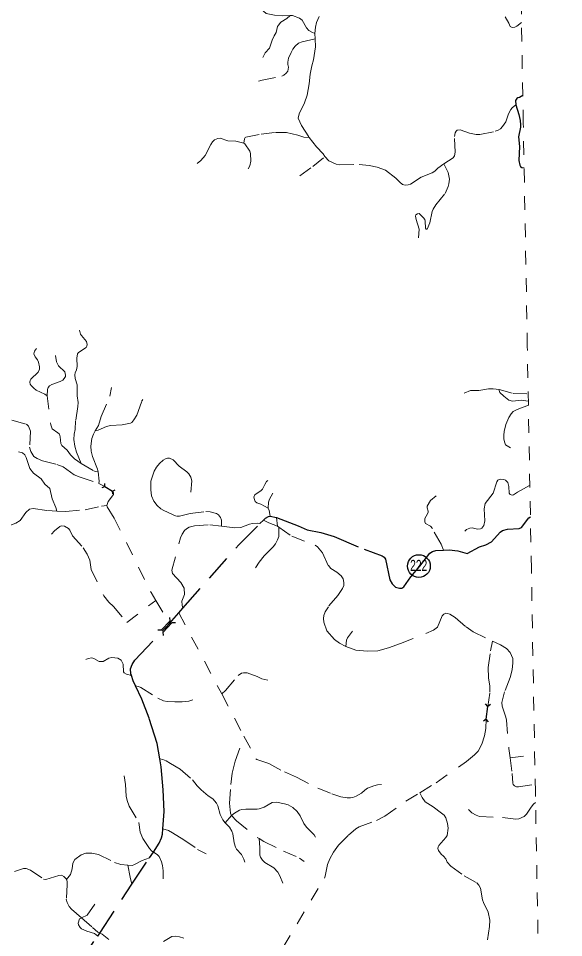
# Model space of a CAD drawing. Extents: x 220.8 to 246.7, y 7287.6 to 7315.8.
# Drawn here: x 242.67 to 246.65, y 7298.43 to 7305.15 of the extents above; entities that cross this region are included whole.
import ezdxf
from ezdxf.enums import TextEntityAlignment as Align

# ---------------------------------------------------------------- set-up
doc = ezdxf.new("R2010")
doc.units = 0
doc.header["$LTSCALE"] = 0.032
for name, pattern in [('DOTTED', [1.5, 0.3, -1.2]), ('LONG_DASHED', [7.5, 6, -1.5]), ('MEDIUM_DASHED', [4.5, 3, -1.5]), ('SHORT_DASHED', [2.7, 1.5, -1.2])]:
    doc.linetypes.add(name, pattern=pattern)
for name, color, linetype, lineweight in [('10', 7, 'Continuous', 25), ('13', 7, 'Continuous', 25), ('31', 7, 'Continuous', 25), ('35', 7, 'SHORT_DASHED', 13), ('4', 7, 'LONG_DASHED', 25), ('6', 7, 'MEDIUM_DASHED', 13), ('7', 7, 'DOTTED', 13)]:
    doc.layers.add(name, color=color, linetype=linetype, lineweight=lineweight)
doc.layers.add('61', color=7, linetype='Continuous')

msp = doc.modelspace()

# ---------------------------------------------------------------- linework, layer by layer
at = {"layer": '10'}
for p, q in [((243.7275, 7300.6631), (243.7911, 7300.7302)), ((243.8161, 7300.7308), (243.7911, 7300.7302)), ((243.7129, 7300.6769), (243.6881, 7300.6764)), ((243.7281, 7300.6383), (243.7275, 7300.6631))]:
    msp.add_line(p, q, dxfattribs=at)
msp.add_lwpolyline([(243.7129, 7300.6769), (243.7766, 7300.7439), (243.776, 7300.769)], dxfattribs=at)
at = {"layer": '13'}
msp.add_circle((245.5943, 7301.145), 0.083, dxfattribs=at)
at = {"layer": '31'}
for p, q in [((243.282, 7301.7179), (243.3016, 7301.7267)), ((243.3016, 7301.7267), (243.3001, 7301.7482)), ((243.3016, 7301.7267), (243.3571, 7301.6934)), ((243.3571, 7301.6934), (243.3768, 7301.7021)), ((243.3586, 7301.6719), (243.3571, 7301.6934)), ((246.0963, 7300.118), (246.0807, 7300.1376)), ((246.0861, 7300.0261), (246.0963, 7300.118)), ((246.1158, 7300.1337), (246.0963, 7300.118)), ((246.0861, 7300.0261), (246.0665, 7300.0107)), ((246.1016, 7300.0067), (246.0861, 7300.0261))]:
    msp.add_line(p, q, dxfattribs=at)
at = {"layer": '35'}
msp.add_lwpolyline([(246.6507, 7288.0853), (246.6212, 7289.7146), (246.5917, 7291.3439), (246.5622, 7292.9732), (246.5328, 7294.6024), (246.5034, 7296.2317), (246.4739, 7297.861), (246.4446, 7299.4903), (246.4152, 7301.1196), (246.3858, 7302.7489), (246.3565, 7304.3782), (246.3272, 7306.0075), (246.2979, 7307.6367), (246.2685, 7309.266), (246.2393, 7310.8953), (246.21, 7312.5246), (246.1808, 7314.1539), (246.1516, 7315.7832)], dxfattribs=at)
at = {"layer": '4'}
for points in [[(246.3528, 7304.5841), (246.3283, 7304.5682), (246.3174, 7304.5671), (246.3098, 7304.5606), (246.3, 7304.5464), (246.3013, 7304.5153), (246.3235, 7304.4455), (246.3337, 7304.4017), (246.3357, 7304.369), (246.3357, 7304.3517), (246.3215, 7304.2814), (246.3276, 7304.2101), (246.3245, 7304.1081), (246.3317, 7304.0745), (246.3368, 7304.0653), (246.3449, 7304.0572), (246.3623, 7304.0553)], [(243.1124, 7298.2445), (243.2485, 7298.4414), (243.2641, 7298.4635), (243.4987, 7298.8213), (243.6276, 7299.0132), (243.6564, 7299.0554), (243.6974, 7299.1205), (243.7149, 7299.1594), (243.7212, 7299.187), (243.7243, 7299.2244), (243.735, 7299.3527), (243.7275, 7299.5096), (243.7124, 7299.679), (243.7024, 7299.7355), (243.6823, 7299.8485), (243.6233, 7300.033), (243.5719, 7300.1723), (243.5239, 7300.2701), (243.5066, 7300.3053), (243.4945, 7300.3445), (243.4903, 7300.358), (243.489, 7300.3932), (243.5003, 7300.4258), (243.5191, 7300.4572), (243.7477, 7300.6989), (243.7734, 7300.7262), (243.8408, 7300.8029), (243.8708, 7300.8371), (244.2797, 7301.3006), (244.4315, 7301.4549), (244.4589, 7301.4807), (244.4743, 7301.4951), (244.4956, 7301.5077), (244.5068, 7301.5085), (244.5538, 7301.4998), (244.7127, 7301.4399), (244.7793, 7301.4098), (244.8772, 7301.391), (244.9751, 7301.3621), (245.1934, 7301.268)], [(245.1934, 7301.268), (245.3265, 7301.219), (245.3415, 7301.209), (245.3491, 7301.1964), (245.3817, 7301.0433), (245.398, 7301.0157), (245.4244, 7300.9918), (245.452, 7300.9843), (245.4696, 7300.9843), (245.4834, 7300.9931), (245.5361, 7301.0671), (245.6013, 7301.145), (245.6741, 7301.2391), (245.693, 7301.2504), (245.7168, 7301.2592), (245.7727, 7301.262), (245.816, 7301.2642), (245.8775, 7301.2554), (245.9477, 7301.2366), (246.0369, 7301.2855), (246.0833, 7301.3006), (246.1235, 7301.3232), (246.1875, 7301.3922), (246.2033, 7301.4049), (246.2402, 7301.4135), (246.3268, 7301.4186), (246.3431, 7301.4274), (246.3958, 7301.4964), (246.4083, 7301.504)]]:
    msp.add_lwpolyline(points, dxfattribs=at)
at = {"layer": '6'}
msp.add_line((244.5625, 7301.4357), (244.5538, 7301.4998), dxfattribs=at)
for points in [[(244.0945, 7305.3468), (244.1381, 7305.3498), (244.2085, 7305.3353), (244.2743, 7305.3292), (244.2873, 7305.3269), (244.3316, 7305.2994), (244.3875, 7305.2887), (244.4051, 7305.2802), (244.415, 7305.2695), (244.4433, 7305.2198), (244.4594, 7305.1999), (244.48, 7305.1831), (244.5404, 7305.1693), (244.5948, 7305.1655), (244.653, 7305.1673), (244.6712, 7305.1678), (244.7217, 7305.1487), (244.7416, 7305.1326), (244.7722, 7305.0776), (244.7913, 7305.0592), (244.8112, 7305.0462), (244.8349, 7305.0363)], [(244.8349, 7305.0363), (244.838, 7305.0814), (244.8472, 7305.1158), (244.867, 7305.1617)], [(246.2246, 7305.1571), (246.2514, 7305.112), (246.2606, 7305.0883), (246.2759, 7305.0806), (246.295, 7305.0821), (246.3088, 7305.089), (246.3432, 7305.1158)], [(244.8349, 7305.0363), (244.8372, 7304.9963), (244.8382, 7304.9397), (244.8235, 7304.8451), (244.8114, 7304.8003), (244.8005, 7304.7396), (244.7929, 7304.6674), (244.7788, 7304.5862), (244.7584, 7304.53), (244.7187, 7304.4482), (244.7129, 7304.4173), (244.736, 7304.3651), (244.7929, 7304.277), (244.8459, 7304.2078), (244.8945, 7304.158), (244.9074, 7304.1384), (244.9367, 7304.1062), (244.9891, 7304.0819), (245.0179, 7304.0768), (245.1591, 7304.0787), (245.232, 7304.0723), (245.2882, 7304.0608), (245.3496, 7304.0385), (245.4263, 7303.979), (245.455, 7303.9496), (245.4755, 7303.9336), (245.4934, 7303.9292), (245.5151, 7303.9298), (245.5333, 7303.9349), (245.6094, 7303.9864), (245.6903, 7304.0186), (245.7101, 7304.0314), (245.7324, 7304.0532), (245.7751, 7304.085), (245.8449, 7304.1273), (245.8545, 7304.1433), (245.8584, 7304.1682), (245.8545, 7304.2833), (245.8584, 7304.3095), (245.8654, 7304.3229), (245.8731, 7304.3293), (245.8948, 7304.3325), (245.9632, 7304.3082), (246.0111, 7304.2992), (246.0399, 7304.2986), (246.1511, 7304.3216), (246.1728, 7304.3299), (246.1888, 7304.3401), (246.2054, 7304.3568), (246.2284, 7304.3913), (246.2495, 7304.4501), (246.2655, 7304.4808), (246.2751, 7304.4929), (246.3013, 7304.5153)], [(242.6205, 7302.2105), (242.7206, 7302.1845), (242.7317, 7302.1799), (242.7437, 7302.1679), (242.7585, 7302.13), (242.7511, 7302.0136), (242.7594, 7301.9812), (242.7825, 7301.9461), (242.8056, 7301.9304), (242.8454, 7301.9128), (242.9507, 7301.887), (242.996, 7301.8694), (243.0764, 7301.8112), (243.1198, 7301.7937), (243.258, 7301.7486), (243.3016, 7301.7267), (243.3571, 7301.6934), (243.3637, 7301.6791), (243.3629, 7301.6679), (243.3241, 7301.618), (243.3143, 7301.5888)], [(242.2041, 7301.3647), (242.2654, 7301.3816), (242.3503, 7301.4274), (242.373, 7301.4322), (242.42, 7301.4378), (242.5319, 7301.4283), (242.5809, 7301.4322), (242.6498, 7301.4593), (242.6833, 7301.4792), (242.7239, 7301.5366), (242.751, 7301.5613), (242.7773, 7301.5668), (242.8816, 7301.5501), (242.9508, 7301.5468), (243.0162, 7301.5437), (243.1572, 7301.5565), (243.2767, 7301.5836), (243.3143, 7301.5888)], [(243.3143, 7301.5888), (243.3182, 7301.5771), (243.3692, 7301.4961), (243.639, 7300.951), (243.6731, 7300.894), (243.7734, 7300.7262)], [(244.4589, 7301.4807), (244.4986, 7301.4609), (244.5625, 7301.4357)], [(244.5625, 7301.4357), (244.5718, 7301.4287), (244.6663, 7301.3637), (244.8356, 7301.2989), (244.8527, 7301.2858), (244.8902, 7301.241), (244.9328, 7301.1489), (244.9498, 7301.1273), (244.9947, 7301.1011), (245.026, 7301.0727), (245.0413, 7301.0506), (245.047, 7301.025), (245.0453, 7301.0028), (245.0368, 7300.9801), (245.0027, 7300.9289), (244.9328, 7300.8482), (244.9084, 7300.8102), (244.8998, 7300.7835), (244.8981, 7300.7619), (244.901, 7300.7363), (244.9214, 7300.6726), (244.9783, 7300.6079), (245.0135, 7300.5817), (245.0617, 7300.5564), (245.1328, 7300.5306), (245.2192, 7300.5226), (245.2931, 7300.5254), (245.3715, 7300.5476), (245.4585, 7300.5783), (245.7017, 7300.6766), (245.7307, 7300.6976), (245.7648, 7300.7823), (245.7756, 7300.7943), (245.7904, 7300.7999), (245.8034, 7300.7988), (245.8199, 7300.7926), (245.8591, 7300.7681), (245.9387, 7300.7005), (245.9904, 7300.6653), (246.1319, 7300.5962)], [(243.8408, 7300.8029), (244.1549, 7300.2103), (244.3169, 7299.902), (244.4038, 7299.7367), (244.4102, 7299.7313), (244.4976, 7299.7015), (244.6127, 7299.6407), (244.7002, 7299.6023), (244.8558, 7299.5213), (244.9582, 7299.4808), (245.0232, 7299.4595), (245.0701, 7299.452), (245.0936, 7299.4509), (245.1106, 7299.4541), (245.1362, 7299.4627), (245.1757, 7299.4861), (245.2002, 7299.5085), (245.2194, 7299.5213), (245.2641, 7299.5394), (245.2908, 7299.5469), (245.3207, 7299.5501)], [(245.6, 7299.4887), (245.7198, 7299.5615), (245.941, 7299.7171), (246.0008, 7299.7655), (246.0262, 7299.7925), (246.0541, 7299.8433), (246.0721, 7299.9056), (246.0828, 7299.9588), (246.0861, 7300.0261), (246.0963, 7300.118), (246.1123, 7300.2226), (246.1114, 7300.2685), (246.1016, 7300.3291), (246.1, 7300.4037), (246.1164, 7300.5249), (246.1319, 7300.5962)], [(246.1319, 7300.5962), (246.1893, 7300.57), (246.2343, 7300.543), (246.2606, 7300.5135), (246.281, 7300.4692), (246.281, 7300.4389), (246.2753, 7300.3873), (246.2597, 7300.3299), (246.2188, 7300.2267), (246.1999, 7300.1489), (246.2016, 7300.1202), (246.2294, 7300.0399), (246.2327, 7300.0203), (246.2507, 7299.813), (246.2596, 7299.7445), (246.2745, 7299.6303), (246.2794, 7299.5598), (246.2827, 7299.5484), (246.2917, 7299.5385), (246.3056, 7299.5328), (246.3204, 7299.5312), (246.4435, 7299.55)], [(244.6024, 7298.3604), (244.9039, 7298.8635), (244.9096, 7298.8798), (244.926, 7298.9634), (244.9432, 7299.006), (244.9694, 7299.0544), (245.0063, 7299.1068), (245.0792, 7299.1781), (245.1332, 7299.2248), (245.157, 7299.2403), (245.2848, 7299.287), (245.3463, 7299.3165), (245.4986, 7299.4271), (245.6, 7299.4887)], [(245.6, 7299.4887), (245.6177, 7299.4549), (245.6409, 7299.4229), (245.6991, 7299.3866), (245.7587, 7299.3401), (245.7783, 7299.3241), (245.7899, 7299.3059), (245.8023, 7299.263), (245.8074, 7299.231), (245.7994, 7299.1765), (245.7907, 7299.162), (245.7391, 7299.1039), (245.734, 7299.0937), (245.7332, 7299.0813), (245.7369, 7299.0661), (245.7558, 7299.0406), (245.7739, 7299.0261), (245.7907, 7299.005), (245.7994, 7298.9818), (245.827, 7298.9512), (245.9251, 7298.8808), (246.0181, 7298.8299), (246.0327, 7298.8139), (246.0436, 7298.7914), (246.0581, 7298.7071), (246.0646, 7298.686), (246.0995, 7298.6169), (246.1112, 7298.5566), (246.1104, 7298.5108), (246.0952, 7298.4142)], [(242.64, 7298.9125), (242.7058, 7298.9347), (242.7254, 7298.9356), (242.7582, 7298.9233), (242.854, 7298.8585), (242.8688, 7298.8561), (242.9655, 7298.8839), (242.9843, 7298.8856), (243.0015, 7298.8774), (243.0179, 7298.861), (243.0199, 7298.8552), (243.0253, 7298.8397), (243.0261, 7298.8176), (243.0195, 7298.7103), (243.0253, 7298.6873), (243.0408, 7298.6578), (243.0564, 7298.6382), (243.1292, 7298.574), (243.2112, 7298.503), (243.2506, 7298.471), (243.2641, 7298.4635), (243.2801, 7298.4546), (243.3292, 7298.417)], [(243.7282, 7298.4014), (243.7905, 7298.4383), (243.815, 7298.4407), (243.8462, 7298.4366), (243.8781, 7298.4252)]]:
    msp.add_lwpolyline(points, dxfattribs=at)
at = {"layer": '7'}
for p, q in [((246.2596, 7299.7445), (246.4396, 7299.767)), ((244.1789, 7299.2698), (244.2265, 7299.323))]:
    msp.add_line(p, q, dxfattribs=at)
for points in [[(244.4549, 7304.8601), (244.4708, 7304.8956), (244.5039, 7304.9301), (244.523, 7304.9879), (244.5365, 7305.02), (244.5514, 7305.0443), (244.5622, 7305.0872), (244.5678, 7305.0974), (244.5859, 7305.1184), (244.6298, 7305.145), (244.653, 7305.1673)], [(244.4237, 7304.6876), (244.4484, 7304.696), (244.592, 7304.7249), (244.6069, 7304.731), (244.6256, 7304.7459), (244.6358, 7304.7613), (244.6419, 7304.7897), (244.6363, 7304.8107), (244.6358, 7304.827), (244.6424, 7304.8569), (244.6605, 7304.8979), (244.6741, 7304.9221), (244.6908, 7304.9431), (244.716, 7304.965), (244.7417, 7304.9757), (244.8372, 7304.9963)], [(244.3146, 7304.2359), (244.3212, 7304.2673), (244.3248, 7304.2755), (244.33, 7304.2786), (244.4415, 7304.3002), (244.5479, 7304.313), (244.627, 7304.314), (244.7108, 7304.294), (244.7535, 7304.2781), (244.7929, 7304.277)], [(243.9748, 7304.0869), (244.0026, 7304.109), (244.0324, 7304.145), (244.074, 7304.2262), (244.0864, 7304.2447), (244.1023, 7304.2585), (244.1254, 7304.2688), (244.1424, 7304.2704), (244.1999, 7304.2524), (244.2585, 7304.2508), (244.3146, 7304.2359)], [(244.3146, 7304.2359), (244.3223, 7304.2298), (244.3593, 7304.1773), (244.3644, 7304.1588), (244.366, 7304.1023), (244.3593, 7304.0684), (244.348, 7304.0468)], [(244.7239, 7303.9973), (244.8203, 7304.0641), (244.9074, 7304.1384)], [(245.5902, 7303.5441), (245.5971, 7303.6069), (245.5735, 7303.6771), (245.5703, 7303.7007), (245.5725, 7303.7109), (245.5843, 7303.7194), (245.5971, 7303.72), (245.6271, 7303.6899), (245.6368, 7303.6771), (245.6405, 7303.6653), (245.6416, 7303.6133), (245.647, 7303.6063), (245.6545, 7303.6058), (245.6743, 7303.6535), (245.692, 7303.7355), (245.699, 7303.7532), (245.7177, 7303.7843), (245.7847, 7303.8679), (245.8083, 7303.9183), (245.8137, 7303.9371), (245.8164, 7303.9714), (245.8132, 7303.9971), (245.8078, 7304.0202), (245.7751, 7304.085)], [(243.1165, 7302.8675), (243.1233, 7302.84), (243.1296, 7302.8286), (243.1663, 7302.7866), (243.1719, 7302.7643), (243.1699, 7302.7508), (243.1649, 7302.7421), (243.1083, 7302.7049), (243.1018, 7302.6969), (243.0957, 7302.6629), (243.0979, 7302.6032), (243.0941, 7302.5797), (243.0846, 7302.5561), (243.0825, 7302.5425), (243.0834, 7302.5164), (243.0989, 7302.4683), (243.0979, 7302.3884), (243.1054, 7302.341), (243.1047, 7302.3103), (243.0875, 7302.2057), (243.0846, 7302.1421), (243.0769, 7302.1078), (243.075, 7302.0696), (243.0825, 7302.0218), (243.095, 7301.9768), (243.129, 7301.8941)], [(242.8011, 7302.7352), (242.7882, 7302.7146), (242.7831, 7302.6954), (242.7925, 7302.6736), (242.8096, 7302.6514), (242.8173, 7302.6352), (242.8241, 7302.6014), (242.8241, 7302.5843), (242.8135, 7302.5617), (242.76, 7302.5108), (242.7545, 7302.5005), (242.7528, 7302.4877), (242.7558, 7302.4745), (242.7622, 7302.4638), (242.7818, 7302.4437), (242.8002, 7302.4313), (242.8626, 7302.4014), (242.8797, 7302.3899)], [(242.8797, 7302.3899), (242.8816, 7302.4354), (242.8869, 7302.4491), (242.8971, 7302.4617), (242.9129, 7302.4715), (242.9743, 7302.4941), (242.9929, 7302.5039), (243.0044, 7302.5146), (243.0128, 7302.5308), (243.0141, 7302.5403), (243.0094, 7302.5642), (242.9632, 7302.6091), (242.9474, 7302.6374), (242.9403, 7302.6826)], [(243.231, 7302.1326), (243.2541, 7302.1732), (243.2741, 7302.2369), (243.3382, 7302.3864), (243.3502, 7302.4488)], [(245.9247, 7302.4093), (245.9711, 7302.4285), (246.0324, 7302.429), (246.1033, 7302.4397), (246.1369, 7302.4408), (246.1793, 7302.4354)], [(246.1793, 7302.4354), (246.1791, 7302.4274), (246.1844, 7302.4136), (246.2137, 7302.3853), (246.2516, 7302.357), (246.2772, 7302.3507), (246.3401, 7302.3565), (246.393, 7302.3496)], [(246.1793, 7302.4354), (246.2831, 7302.4066), (246.392, 7302.4035)], [(242.8797, 7302.3899), (242.907, 7302.177), (242.9152, 7302.148), (242.9583, 7302.1189), (242.9686, 7302.1087), (242.9741, 7302.0899), (242.9788, 7302.0399), (242.987, 7302.0253), (243.025, 7301.992), (243.0489, 7301.9578), (243.0797, 7301.9287), (243.129, 7301.8941)], [(243.231, 7302.1326), (243.2523, 7302.1386), (243.3126, 7302.1651), (243.3429, 7302.1732), (243.4267, 7302.1758), (243.487, 7302.1886), (243.4972, 7302.1946), (243.5126, 7302.2129), (243.5348, 7302.2484), (243.5694, 7302.3471), (243.5788, 7302.3621)], [(246.2628, 7302.0083), (246.2276, 7302.0317), (246.2207, 7302.0456), (246.2153, 7302.0733), (246.2143, 7302.1011), (246.2169, 7302.1288), (246.2292, 7302.1805), (246.2505, 7302.2301), (246.2671, 7302.2573), (246.2825, 7302.2739), (246.3119, 7302.2888), (246.3935, 7302.3213)], [(243.2509, 7301.8339), (243.2464, 7301.854), (243.2096, 7301.9463), (243.2015, 7301.9834), (243.1989, 7302.0202), (243.2053, 7302.077), (243.2169, 7302.1078), (243.231, 7302.1326)], [(242.671, 7301.9804), (242.6988, 7301.9736), (242.7159, 7301.9588), (242.7254, 7301.9394), (242.7527, 7301.8584), (242.779, 7301.8231), (242.8348, 7301.7824), (242.8622, 7301.7436), (242.8979, 7301.711), (242.9162, 7301.6353), (242.9431, 7301.573), (242.9508, 7301.5468)], [(243.9287, 7301.6838), (243.9371, 7301.7683), (243.9298, 7301.7952), (243.9147, 7301.8179), (243.8995, 7301.8344), (243.8434, 7301.8753), (243.8001, 7301.9208), (243.7738, 7301.9328), (243.7592, 7301.9328), (243.7445, 7301.9284), (243.7272, 7301.9184), (243.699, 7301.894), (243.6774, 7301.868), (243.6603, 7301.8385), (243.637, 7301.7648), (243.6367, 7301.7012), (243.6411, 7301.6592), (243.6595, 7301.6188), (243.6828, 7301.5885), (243.7104, 7301.5636), (243.7313, 7301.5516), (243.8272, 7301.5088), (243.8461, 7301.5088), (243.9236, 7301.53), (244.0393, 7301.543), (244.0707, 7301.5419), (244.1156, 7301.5294), (244.1303, 7301.5186), (244.1454, 7301.4996), (244.1517, 7301.4796), (244.1528, 7301.4368)], [(243.129, 7301.8941), (243.2199, 7301.8407), (243.231, 7301.836), (243.2509, 7301.8339)], [(243.258, 7301.7486), (243.2592, 7301.7651), (243.2509, 7301.8339)], [(244.4911, 7301.7696), (244.4821, 7301.7618), (244.4682, 7301.7399), (244.4524, 7301.7071), (244.4414, 7301.696), (244.397, 7301.6666), (244.3899, 7301.6495), (244.3927, 7301.6305), (244.3995, 7301.6173), (244.4113, 7301.6069), (244.4396, 7301.5976), (244.4946, 7301.568)], [(245.9293, 7301.4006), (245.9418, 7301.4131), (245.9657, 7301.4216), (245.9839, 7301.4233), (246.0231, 7301.4142), (246.0442, 7301.4171), (246.0533, 7301.4222), (246.0686, 7301.4404), (246.0743, 7301.4756), (246.0715, 7301.5644), (246.0783, 7301.6019), (246.1352, 7301.6781), (246.1636, 7301.7611), (246.1704, 7301.7731), (246.1875, 7301.7799), (246.2148, 7301.7765), (246.2273, 7301.7719), (246.2427, 7301.756), (246.2512, 7301.7264), (246.2535, 7301.6781), (246.2597, 7301.6684), (246.2683, 7301.665), (246.2785, 7301.6633), (246.2853, 7301.6662), (246.3143, 7301.6855), (246.4041, 7301.7338)], [(244.4946, 7301.568), (244.4961, 7301.6123), (244.5032, 7301.6348), (244.5275, 7301.6777)], [(245.7727, 7301.262), (245.7555, 7301.3062), (245.6928, 7301.4185), (245.6789, 7301.4371), (245.6431, 7301.4569), (245.6362, 7301.4692), (245.6382, 7301.4927), (245.658, 7301.5259), (245.6614, 7301.5378), (245.6627, 7301.5471), (245.6551, 7301.5699), (245.6551, 7301.5819), (245.6792, 7301.623), (245.7203, 7301.6594)], [(244.4946, 7301.568), (244.5014, 7301.5519), (244.5068, 7301.5085)], [(244.1528, 7301.4368), (244.25, 7301.4246), (244.295, 7301.4276), (244.3575, 7301.4506), (244.3795, 7301.4557), (244.4133, 7301.4587), (244.4315, 7301.4549)], [(242.9118, 7301.3771), (242.9327, 7301.4027), (242.9711, 7301.4336), (242.9825, 7301.4388), (243.0062, 7301.4378), (243.0347, 7301.4198), (243.0446, 7301.4065), (243.065, 7301.3648), (243.1428, 7301.278), (243.1727, 7301.2325), (243.1921, 7301.1893), (243.2021, 7301.1192), (243.2926, 7300.9276), (243.3296, 7300.8825), (243.3643, 7300.8503), (243.4615, 7300.7331), (243.6731, 7300.894)], [(243.8708, 7300.8371), (243.8646, 7300.8594), (243.864, 7300.8896), (243.8819, 7300.9363), (243.8805, 7300.9827), (243.8566, 7301.0251), (243.7951, 7301.0918), (243.7901, 7301.1149), (243.8528, 7301.3513), (243.8646, 7301.3774), (243.8827, 7301.4049), (243.8981, 7301.4183), (243.9168, 7301.429), (243.9558, 7301.44), (244.0685, 7301.4461), (244.1528, 7301.4368)], [(244.4016, 7301.1323), (244.4268, 7301.1735), (244.4632, 7301.2194), (244.53, 7301.2864), (244.5471, 7301.3082), (244.5625, 7301.3356), (244.5718, 7301.3614), (244.5718, 7301.4287)], [(245.0617, 7300.5564), (245.0644, 7300.6028), (245.0729, 7300.6219), (245.1104, 7300.6683)], [(243.163, 7300.4628), (243.179, 7300.4703), (243.2064, 7300.4738), (243.2199, 7300.4698), (243.2588, 7300.4484), (243.2877, 7300.4469), (243.3297, 7300.4713), (243.3521, 7300.4763), (243.3955, 7300.4728), (243.4199, 7300.4573), (243.4279, 7300.4439), (243.4339, 7300.4284), (243.4374, 7300.373), (243.4424, 7300.365), (243.4594, 7300.3546), (243.4945, 7300.3445)], [(244.1549, 7300.2103), (244.1827, 7300.2358), (244.2732, 7300.3443), (244.2978, 7300.3618), (244.3126, 7300.3654), (244.3406, 7300.365), (244.413, 7300.3383), (244.4474, 7300.3218), (244.492, 7300.3123)], [(243.5239, 7300.2701), (243.5477, 7300.2653), (243.5641, 7300.2583), (243.6878, 7300.18), (243.7297, 7300.1615), (243.7562, 7300.1565), (243.8126, 7300.1525), (243.8659, 7300.152), (243.9133, 7300.158), (243.9442, 7300.1675)], [(244.2265, 7299.323), (244.2194, 7299.3398), (244.2117, 7299.4132), (244.2204, 7299.5498), (244.2311, 7299.6309), (244.253, 7299.7206), (244.3169, 7299.902)], [(243.7024, 7299.7355), (243.7239, 7299.7328), (243.7497, 7299.7226), (243.78, 7299.7017), (243.8502, 7299.6617), (243.941, 7299.582), (243.9744, 7299.5389), (244.0046, 7299.5091), (244.0558, 7299.4659), (244.0896, 7299.4432), (244.1163, 7299.4116), (244.1256, 7299.3943), (244.1434, 7299.3293), (244.1616, 7299.2906), (244.1789, 7299.2698)], [(243.443, 7299.6122), (243.4512, 7299.549), (243.457, 7299.4627), (243.4628, 7299.4318), (243.4787, 7299.3917), (243.5491, 7299.2702), (243.5593, 7299.2002), (243.5771, 7299.1553), (243.6273, 7299.0806), (243.6447, 7299.0627), (243.6564, 7299.0554), (243.6828, 7299.0381), (243.6963, 7299.0236), (243.7151, 7298.9841), (243.7228, 7298.958), (243.7276, 7298.9189), (243.7272, 7298.861)], [(244.2265, 7299.323), (244.2466, 7299.3403), (244.2849, 7299.3624), (244.3012, 7299.3669), (244.3292, 7299.3686), (244.4138, 7299.3683), (244.4276, 7299.371), (244.4639, 7299.3835), (244.5227, 7299.4167), (244.5534, 7299.4198), (244.6115, 7299.4084), (244.6402, 7299.3994), (244.6726, 7299.3821), (244.7055, 7299.352), (244.7262, 7299.3206), (244.7531, 7299.2643), (244.7728, 7299.238), (244.8302, 7299.1813), (244.8385, 7299.1651)], [(245.956, 7299.366), (245.9812, 7299.3425), (246.0122, 7299.3247), (246.0363, 7299.3155), (246.2056, 7299.3075), (246.3008, 7299.2949), (246.3249, 7299.2972), (246.3628, 7299.3155), (246.3789, 7299.3316), (246.4133, 7299.3844), (246.4317, 7299.4062), (246.4459, 7299.4177)], [(244.2265, 7299.323), (244.2622, 7299.2837), (244.4131, 7299.1614), (244.4265, 7299.1534)], [(244.1789, 7299.2698), (244.2115, 7299.2368), (244.2284, 7299.2092), (244.2364, 7299.1883), (244.2453, 7299.1238), (244.2546, 7299.09), (244.2613, 7299.0767), (244.2982, 7299.0371), (244.316, 7299.0046), (244.324, 7298.9815)], [(243.7243, 7299.2244), (243.7648, 7299.2123), (243.7957, 7299.1954), (243.8777, 7299.1457), (243.9771, 7299.0752), (244.0417, 7299.0434)], [(244.4265, 7299.1534), (244.432, 7299.089), (244.433, 7299.0324), (244.4381, 7299.0186), (244.4524, 7298.9952), (244.4682, 7298.9799), (244.5344, 7298.9391), (244.563, 7298.908), (244.5778, 7298.882), (244.6002, 7298.829)], [(244.4265, 7299.1534), (244.462, 7299.1323), (244.6053, 7299.0625), (244.7226, 7299.012), (244.7557, 7298.9875)], [(243.0199, 7298.8552), (243.05, 7298.8925), (243.0619, 7298.9324), (243.0675, 7298.9744), (243.0819, 7299.0008), (243.1275, 7299.0343), (243.1622, 7299.0471), (243.2054, 7299.0479), (243.2541, 7299.0383), (243.3719, 7298.98), (243.4187, 7298.9656), (243.4694, 7298.9585)], [(243.4694, 7298.9585), (243.5006, 7298.9584), (243.5134, 7298.9616), (243.5725, 7298.9928), (243.6276, 7299.0132)], [(243.4694, 7298.9585), (243.485, 7298.8717), (243.4987, 7298.8213)], [(243.2485, 7298.4414), (243.2262, 7298.4612), (243.1705, 7298.4773), (243.1299, 7298.4955), (243.1197, 7298.5051), (243.1075, 7298.5245), (243.1065, 7298.5364), (243.1147, 7298.5681), (243.1292, 7298.574), (243.1712, 7298.5935), (243.2338, 7298.6842)]]:
    msp.add_lwpolyline(points, dxfattribs=at)

# ---------------------------------------------------------------- texts
at = {"layer": '61', "width": 0.7}
msp.add_text('222', height=0.08, dxfattribs=at).set_placement((245.5925, 7301.1102), align=Align.CENTER)

doc.saveas('drawing.dxf')
